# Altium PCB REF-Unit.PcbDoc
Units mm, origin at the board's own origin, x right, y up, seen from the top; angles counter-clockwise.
Board outline 28.96 x 18.29 mm, 4 copper layers (Top1, Signal2, Gnd3, Bottom4), stack 1.043 mm thick; 43 components, 73 nets, 248 pads, 219 vias.
Unrouted connection lines stored in the file: 57.
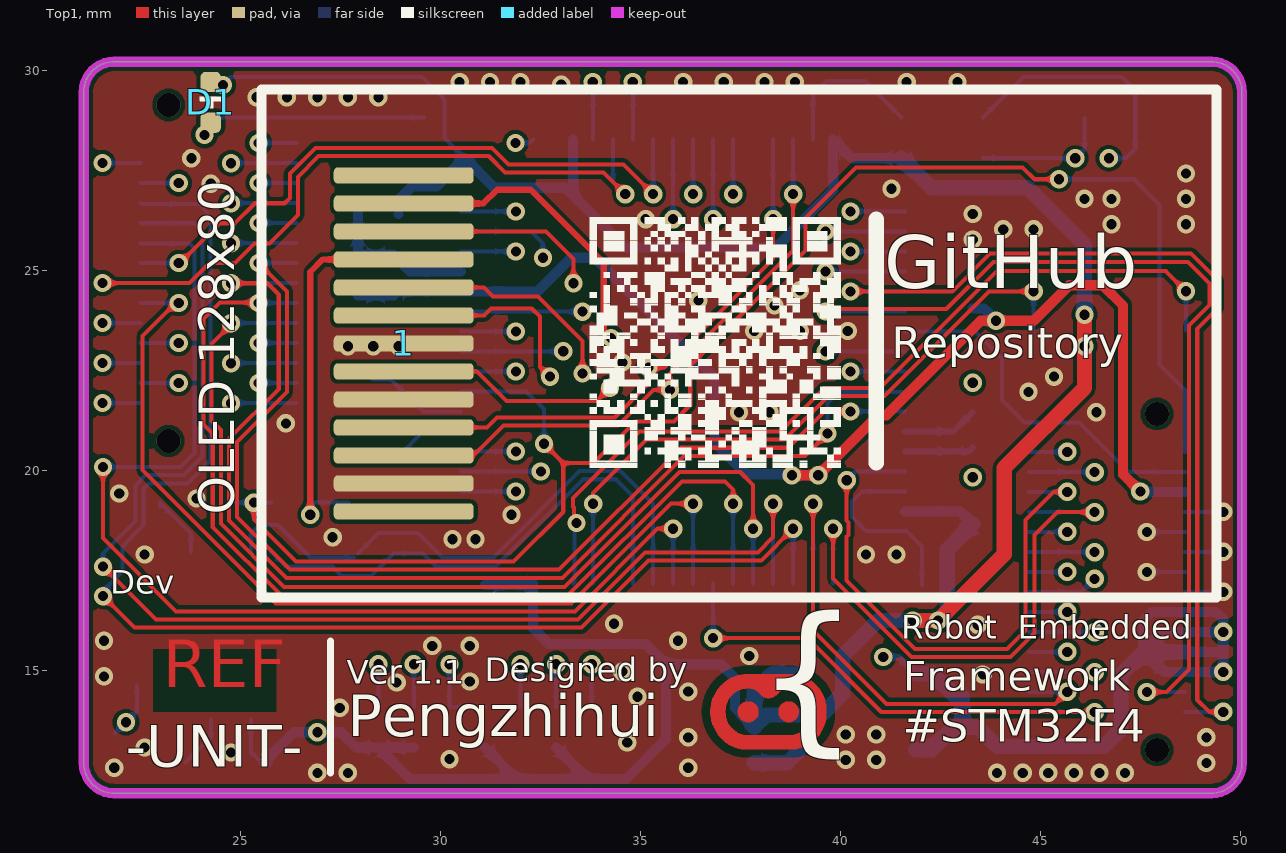
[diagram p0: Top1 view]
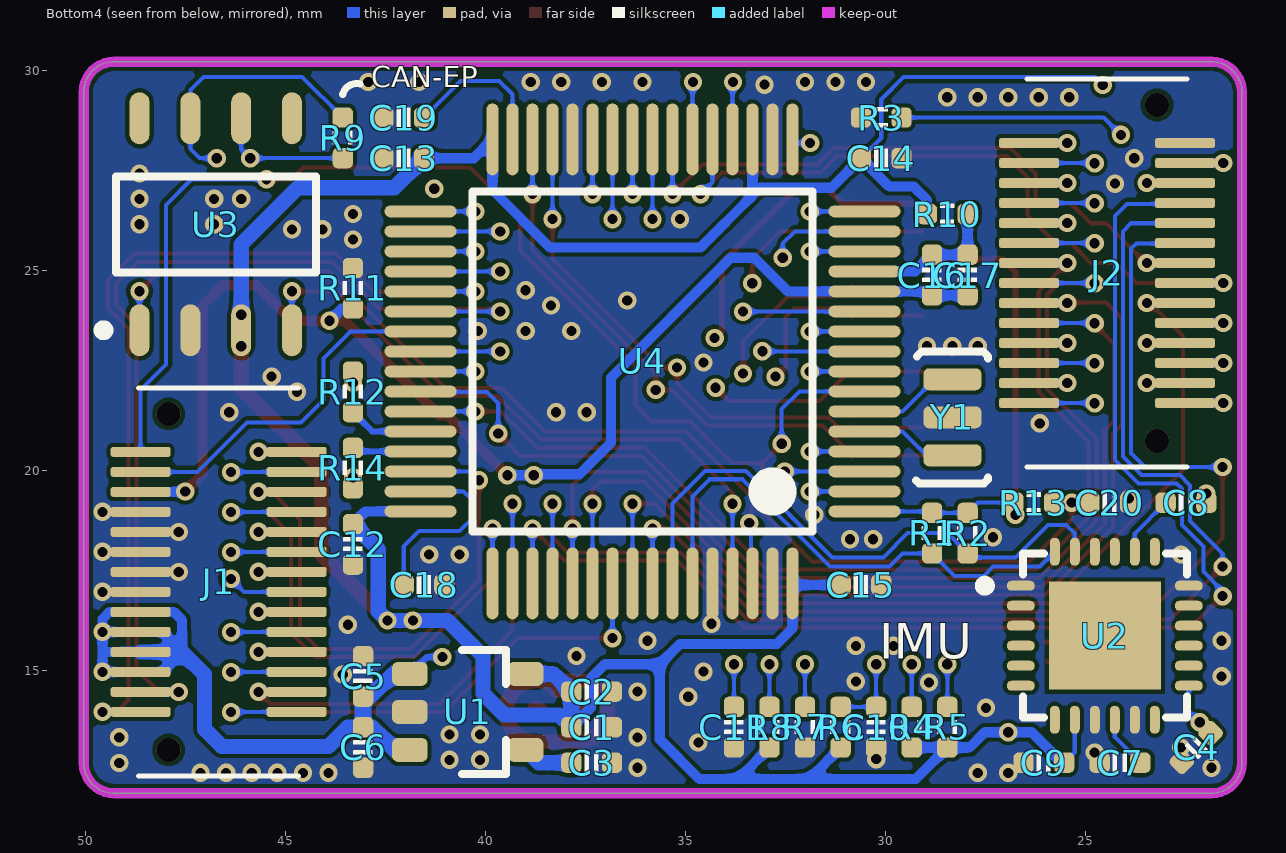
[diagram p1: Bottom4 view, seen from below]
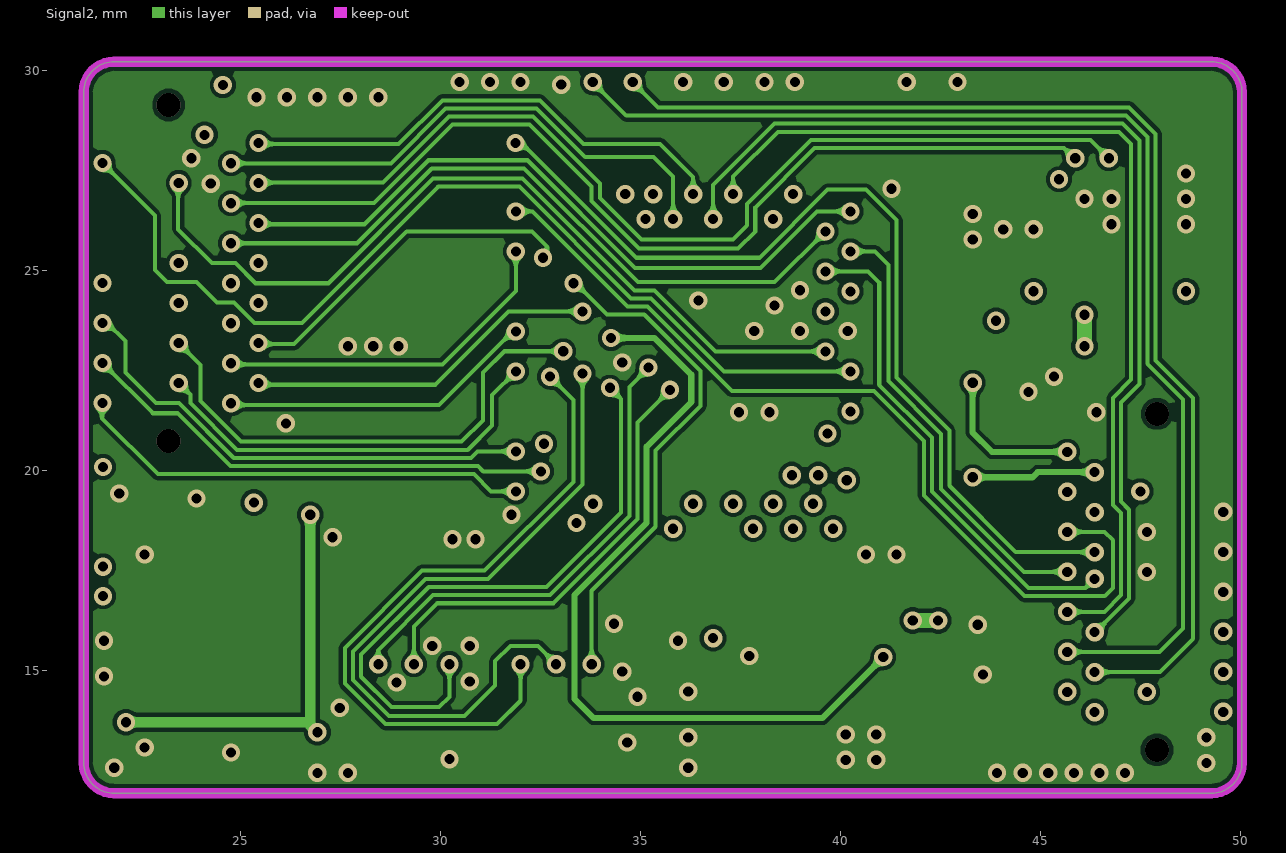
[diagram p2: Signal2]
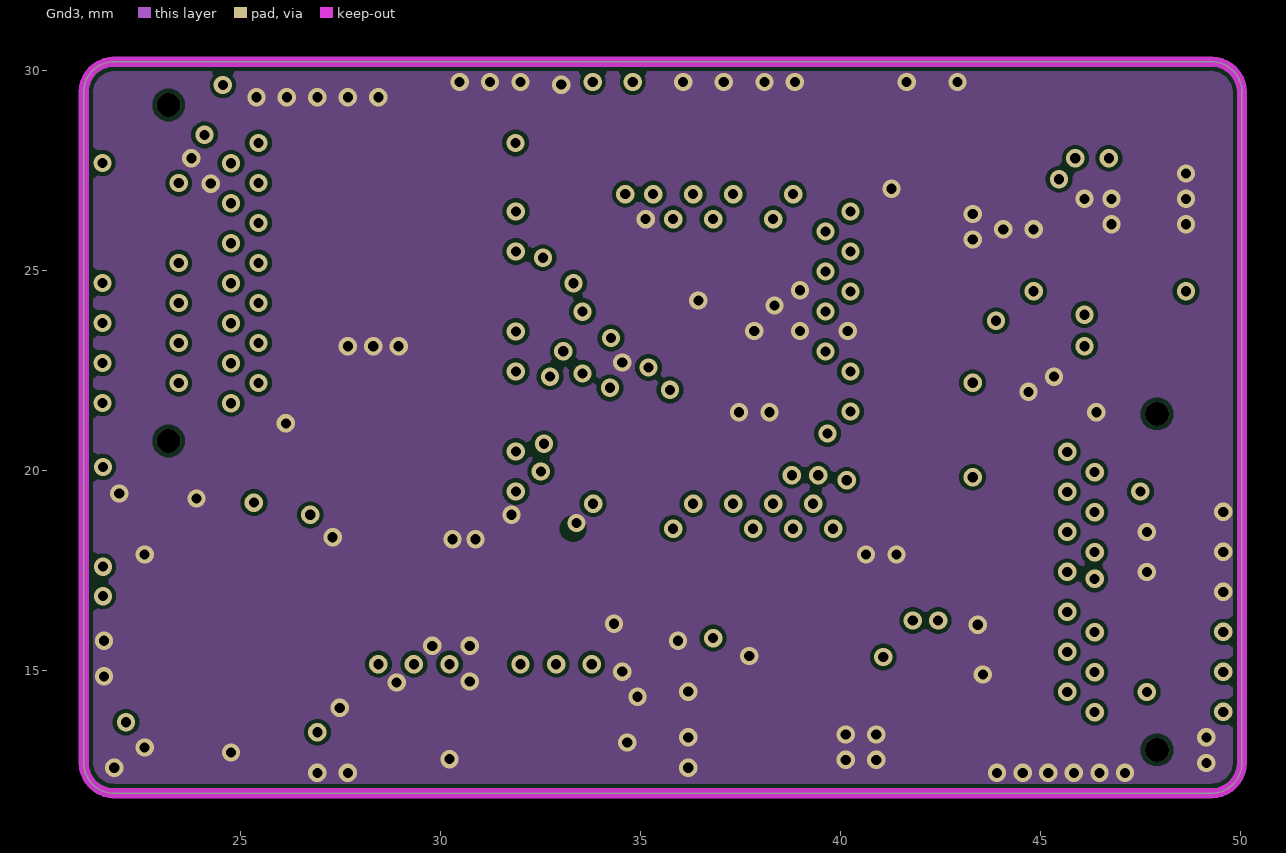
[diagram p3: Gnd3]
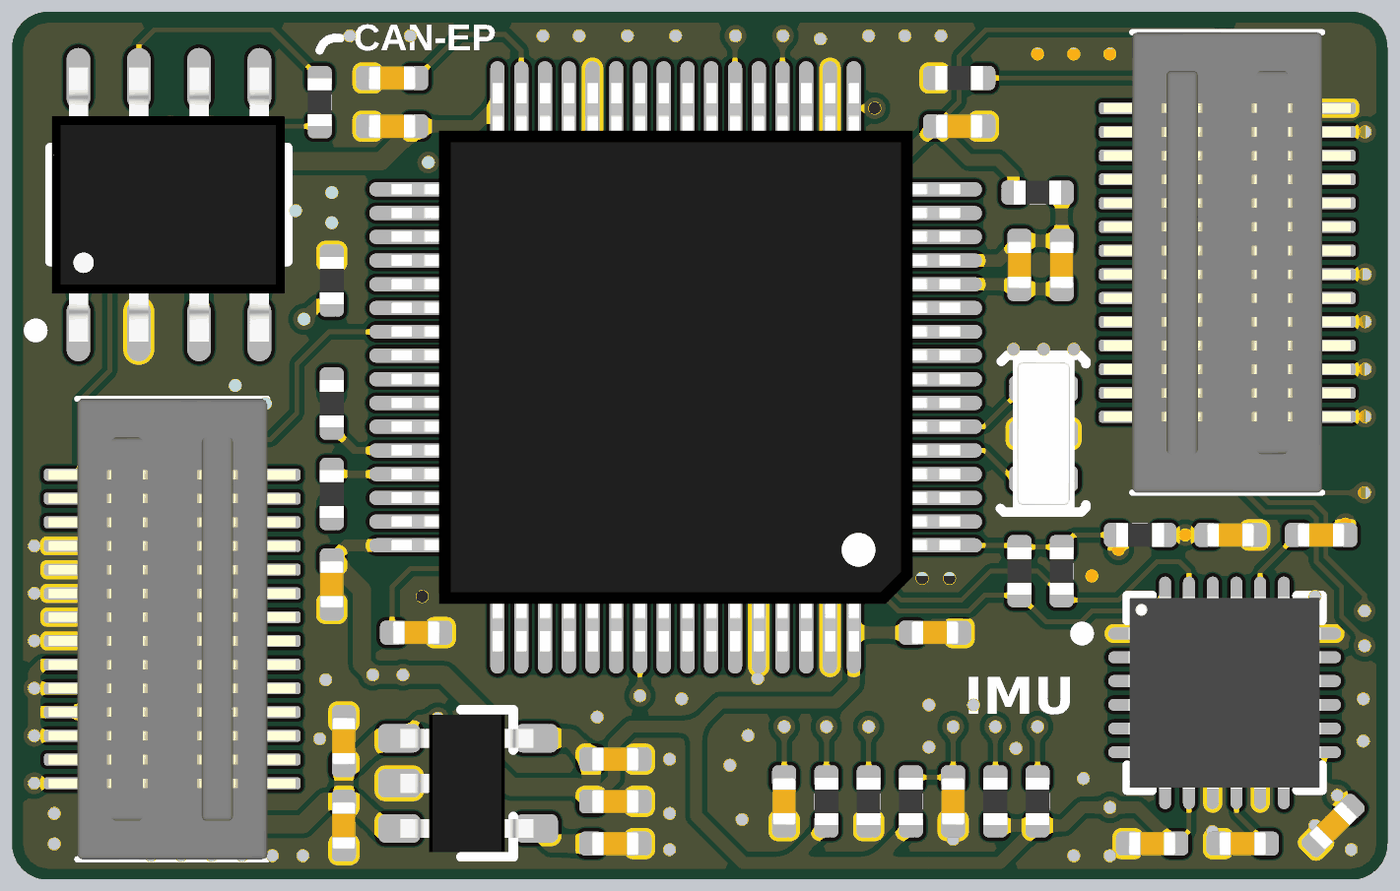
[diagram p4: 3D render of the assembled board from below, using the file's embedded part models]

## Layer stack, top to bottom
Top Solder: solder mask 0.0102, Solder Resist, Dk 3.5
Top1: signal copper 0.0356
Dielectric1: core 0.3, FR-4, Dk 4.2
Signal2: signal copper 0.036
Dielectric 4: prepreg 0.3, Dk 4.2
Gnd3: signal copper 0.036
Dielectric 3: core 0.3, Dk 4.2
Bottom4: signal copper 0.0356
Bottom Solder: solder mask 0.0102, Solder Resist, Dk 3.5

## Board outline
21.082,12.7 ccw(c21.844,12.7) 21.844,11.938 49.276,11.938 ccw(c49.276,12.7) 50.038,12.7 50.038,29.464 ccw(c49.276,29.464) 49.276,30.226 21.844,30.226 ccw(c21.844,29.464) 21.082,29.464

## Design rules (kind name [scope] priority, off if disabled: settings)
Clearance Clearance_Logo [InNetClass('Logo')] p1: gap=0.203 ignorepadtopadclearanceinfootprint=FALSE
Clearance [All] p2: gap=0.102 ignorepadtopadclearanceinfootprint=FALSE except(0: Arc-Hole Track-Hole SMDPad-Hole THPad-Hole Via-Hole Fill-Hole Poly-Hole Region-Hole Text-Hole)
ComponentClearance [All] p1: gap=0 collisioncheckmode=3 verticalgap=0 showdistances=FALSE
DiffPairsRouting [All] p1: maxlimit=0.229 minlimit=0.229 mostfreqgap=0.229 toplayer_minwidth=0.381 toplayer_maxwidth=0.381 toplayer_prefwidth=0.381 midlayer1_minwidth=0.381 midlayer1_maxwidth=0.381 midlayer1_prefwidth=0.381 midlayer2_minwidth=0.381 midlayer2_maxwidth=0.381 midlayer2_prefwidth=0.381 bottomlayer_minwidth=0.381 bottomlayer_maxwidth=0.381 bottomlayer_prefwidth=0.381 maxuncoupledlength=12.7
FanoutControl Fanout_BGA [All] p1: bgadir=Out bgaviamode=Centered fanoutstyle=Auto fanoutdirection=Alternating viagrid=0.025 // Fanout_BGA (Default Rule)
HoleSize [All] p1: absolutevalues=TRUE maxlimit=254 minlimit=0.203 maxpercent=80.000 minpercent=20.000
MinimumSolderMaskSliver [All] p1 off: minsoldermaskwidth=0.051
PlaneClearance [All] p1: clearance=0.203
PlaneConnect [All] p1: planeconnectstyle=Direct reliefexpansion=0.508 reliefentries=4 reliefconductorwidth=0.254 reliefairgap=0.254
PolygonConnect [All] p1: connectstyle=Direct reliefconductorwidth=0.254 reliefentries=4 polygonreliefangle="90 Angle" airgapwidth=0.254
RoutingVias [All] p1: holewidth=0.203 width=0.406 viastyle="Through Hole" minholewidth=0.152 minwidth=0.305 maxholewidth=0.711 maxwidth=1.27
SilkToSilkClearance [All] p1: silktosilkclearance=0
SilkToSolderMaskClearance [IsPad] p1: minsilkscreentomaskgap=0 clearancetoexposedcopper=TRUE
SolderMaskExpansion [All] p1: expansion=0.076 istentingtop=FALSE
Width Logo [InNetClass('Logo')] p1: maxlimit=2.54 minlimit=0.003 preferedwidth=0.254
Width GND [(InNet('AGND') OR InNet('GND'))] p2: maxlimit=1.27 minlimit=0.102 preferedwidth=0.254
Width VCC [(InNet('VDD_SYS_3.3V') OR InNet('VDD_AV_3.3V') OR InNet('VDD_5V') OR InNet('VDD1V2-SYS') OR InNet('VDD1V1-EPHY') OR InNet('VDD-CPUX') OR InNet('VDD-CPUS') OR InNet('VDD-CPUFB') OR InNet('VCC-DRAM'))] p3: maxlimit=1.27 minlimit=0.102 preferedwidth=0.254
Width [All] p4: maxlimit=254 minlimit=0.102 preferedwidth=0.102
21 further rules are at their usual default settings.

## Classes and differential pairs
net class Logo: LOGO1 LOGO2 LOGO3
net class Encoder: ENCODER1_A_1 ENCODER1_B_1 ENCODER2_A_1 ENCODER2_B_1
net class CAN: CAN1_H_1 CAN1_L_1 CAN2_D_1 CAN2_R_1
net class GPIO: PA4_1 PA6_1 PB0_1 PB1_1 PC0_1 PC1_1 PC8_1 PC13_1 PC14_1 PC15_1
net class ADC: ADC1_1 ADC2_1 ADC3_1 ADC4_1
net class PWM: PWM_A1_1 PWM_A2_1 PWM_B1_1 PWM_B2_1
net class I2C: I2C_SCL_1 I2C_SDA_1
net class SPI: SPI1_MISO_1 SPI1_MOSI_1 SPI1_SCK_1 SPI3_MISO_1 SPI3_MOSI_1 SPI3_SCK_1
net class UART: UART1_Rx_1 UART1_Tx_1 UART4_Rx_1 UART4_Tx_1 UART5_Rx_1 UART5_Tx_1
net class USB: USB_DM_1 USB_DP_1

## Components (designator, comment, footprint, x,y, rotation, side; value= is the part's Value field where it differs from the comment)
1 "OLED-12880" OLED-12880 29.083,23.182 r180 top locked
C1 "0.1uF" CAP_0402 37.338,13.589 r0 bottom value=0.1u
C2 "10uF" CAP_0402 37.338,14.478 r0 bottom value=0.1u
C3 "10nF" CAP_0402 37.338,12.7 r0 bottom value=0.1u
C4 "10nF" CAP_0402 22.225,13.081 r315 bottom value=0.1u
C5 "10uF" CAP_0402 43.053,14.859 r270 bottom value=0.1u
C6 "0.1uF" CAP_0402 43.053,13.081 r90 bottom value=0.1u
C7 "0.1uF" CAP_0402 24.13,12.7 r0 bottom value=0.1u
C8 "2.2nF" CAP_0402 22.479,19.202 r0 bottom value=0.1u
C9 "0.1uF" CAP_0402 26.035,12.7 r180 bottom value=0.1u
C10 "10uF" CAP_0402 30.226,13.589 r90 bottom value=0.1u
C11 "10uF" CAP_0402 33.782,13.589 r90 bottom value=0.1u
C12 "0.1uF" CAP_0402 43.307,18.161 r90 bottom value=0.1u
C13 "0.1uF" CAP_0402 42.037,27.813 r180 bottom value=0.1u
C14 "0.1uF" CAP_0402 30.099,27.813 r0 bottom value=0.1u
C15 "0.1uF" CAP_0402 30.607,17.145 r0 bottom value=0.1u
C16 "0.1uF" CAP_0402 28.829,24.892 r90 bottom value=0.1u
C17 "10uF" CAP_0402 27.94,24.892 r90 bottom value=0.1u
C18 "10uF" CAP_0402 41.529,17.145 r0 bottom value=0.1u
C19 "10uF" CAP_0402 42.037,28.829 r180 bottom value=0.1u
C20 "0.1uF" CAP_0402 24.384,19.202 r0 bottom value=0.1u
D1 "color?" LED_0402_RED 24.257,29.21 r270 top
J1 "B2B-Connector-28P-0.5mm" B2B-0.5mm-28P-M 46.666,17.22 r270 bottom locked
J2 "B2B-Connector-28P-0.5mm" B2B-0.5mm-28P-M 24.454,24.944 r90 bottom
R1 "2K" RES_0402 28.829,18.44 r90 bottom value=22R
R2 "2K" RES_0402 27.94,18.44 r90 bottom value=22R
R3 "2K" RES_0402 30.099,28.829 r180 bottom value=22R
R4 "4.7K" RES_0402 29.337,13.589 r270 bottom value=22R
R5 "4.7K" RES_0402 28.448,13.589 r270 bottom value=22R
R6 "10K" RES_0402 31.115,13.589 r270 bottom value=22R
R7 "560K" RES_0402 32.004,13.589 r270 bottom value=22R
R8 "4.7K" RES_0402 32.893,13.589 r270 bottom value=22R
R9 "120R/NC" RES_0402 43.561,28.321 r270 bottom value=22R
R10 "0R" RES_0402 28.448,26.416 r0 bottom value=22R
R11 "0R" RES_0402 43.307,24.562 r90 bottom value=22R
R12 "22R" RES_0402 43.307,21.971 r270 bottom
R13 "10K" RES_0402 26.289,19.202 r0 bottom value=22R
R14 "22R" RES_0402 43.307,20.066 r90 bottom
U1 "LP2992 3V3" SOT23-5 40.386,13.97 r180 bottom
U2 "MPU6050" QFN-24 24.511,15.875 r180 bottom
U3 "SN65HVD232D" SO-8 46.736,26.162 r90 bottom
U4 "STM32F405RGT6" LQFP-64_N 36.068,22.733 r0 bottom locked
Y1 "8MHz" 晶振-3P 28.321,21.336 r90 bottom

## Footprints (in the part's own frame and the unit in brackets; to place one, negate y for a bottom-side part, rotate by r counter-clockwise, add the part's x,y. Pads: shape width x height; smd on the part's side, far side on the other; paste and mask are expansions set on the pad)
B2B-0.5mm-28P-M [mm]
  rrect50% 0.25x1.5 smd: 1(-3.251,1.95) 2(-3.251,-1.95) 3(-2.751,1.95) 4(-2.751,-1.95) 5(-2.251,1.95) 6(-2.251,-1.95) 7(-1.751,1.95) 8(-1.751,-1.95) 9(-1.251,1.95) 10(-1.251,-1.95) 11(-0.751,1.95) 12(-0.751,-1.95) 13(-0.251,1.95) 14(-0.251,-1.95) 15(0.249,1.95) 16(0.249,-1.95) 17(0.749,1.95) 18(0.749,-1.95) 19(1.249,1.95) 20(1.249,-1.95) 21(1.749,1.95) 22(1.749,-1.95) 23(2.249,1.95) 24(2.249,-1.95) 25(2.749,1.95) 26(2.749,-1.95) 27(3.249,1.95) 28(3.249,-1.95)
  round 0.6 hole 0.6 unplated: ""(-4.2,-1.25) ""(4.2,-1.25)
  silkscreen extent -4.85,-2 4.85,2, body extent -4.85,-2.6 4.85,2.6, height 2.7
CAP_0402 [mil]
  rrect50% 20x20 smd: 1(-20,0) 2(20,0)
  silkscreen extent -6,-9 6,9, body extent -20,-10 20,10, height 20
LED_0402_RED [mil]
  rrect50% 20x20 smd: 1(-20,0) 2(20,0)
  silkscreen extent -6,-11 6,10, body extent -20,-10 20,10, height 18
LQFP-64_N [mm] "Thin QFP, 64-Leads, Body 10x10mm, Pitch 0.5mm, IPC Medium Density"
  oval 1.8x0.3 smd: 1(-5.55,3.75) 2(-5.55,3.25) 3(-5.55,2.75) 4(-5.55,2.25) 5(-5.55,1.75) 6(-5.55,1.25) 7(-5.55,0.75) 8(-5.55,0.25) 9(-5.55,-0.25) 10(-5.55,-0.75) 11(-5.55,-1.25) 12(-5.55,-1.75) 13(-5.55,-2.25) 14(-5.55,-2.75) 15(-5.55,-3.25) 16(-5.55,-3.75) 33(5.55,-3.75) 34(5.55,-3.25) 35(5.55,-2.75) 36(5.55,-2.25) 37(5.55,-1.75) 38(5.55,-1.25) 39(5.55,-0.75) 40(5.55,-0.25) 41(5.55,0.25) 42(5.55,0.75) 43(5.55,1.25) 44(5.55,1.75) 45(5.55,2.25) 46(5.55,2.75) 47(5.55,3.25) 48(5.55,3.75)
  oval 0.3x1.8 smd: 17(-3.75,-5.55) 18(-3.25,-5.55) 19(-2.75,-5.55) 20(-2.25,-5.55) 21(-1.75,-5.55) 22(-1.25,-5.55) 23(-0.75,-5.55) 24(-0.25,-5.55) 25(0.25,-5.55) 26(0.75,-5.55) 27(1.25,-5.55) 28(1.75,-5.55) 29(2.25,-5.55) 30(2.75,-5.55) 31(3.25,-5.55) 32(3.75,-5.55) 49(3.75,5.55) 50(3.25,5.55) 51(2.75,5.55) 52(2.25,5.55) 53(1.75,5.55) 54(1.25,5.55) 55(0.75,5.55) 56(0.25,5.55) 57(-0.25,5.55) 58(-0.75,5.55) 59(-1.25,5.55) 60(-1.75,5.55) 61(-2.25,5.55) 62(-2.75,5.55) 63(-3.25,5.55) 64(-3.75,5.55)
  silkscreen extent -4.25,-4.25 4.25,4.25, body extent -5.99,-5.99 5.98,5.98, height 1.6
OLED-12880 [mm]
  rrect50% 3.5x0.4 smd: 1(0,-4.2) 2(0,-3.5) 3(0,-2.8) 4(0,-2.1) 5(0,-1.4) 6(0,-0.7) 7(0,0) 8(0,0.7) 9(0,1.4) 10(0,2.1) 11(0,2.8) 12(0,3.5) 13(0,4.2)
  silkscreen extent -20.32,-6.35 3.56,6.35, body extent -20.18,-6.25 7.54,6.25, height 1.55
QFN-24 [mm] "QFN, 24-Leads, Body 4.1x4.1mm (max), Pitch 0.50mm, IPC Low Density"
  oval 0.7x0.25 smd: 1(-2.1,1.25) 2(-2.1,0.75) 3(-2.1,0.25) 4(-2.1,-0.25) 5(-2.1,-0.75) 6(-2.1,-1.25) 13(2.1,-1.25) 14(2.1,-0.75) 15(2.1,-0.25) 16(2.1,0.25) 17(2.1,0.75) 18(2.1,1.25)
  oval 0.25x0.7 smd: 7(-1.25,-2.1) 8(-0.75,-2.1) 9(-0.25,-2.1) 10(0.25,-2.1) 11(0.75,-2.1) 12(1.25,-2.1) 19(1.25,2.1) 20(0.75,2.1) 21(0.25,2.1) 22(-0.25,2.1) 23(-0.75,2.1) 24(-1.25,2.1)
  rect 2.8x2.7 smd: ""(0,0)
  silkscreen extent -3.13,-2.05 2.05,2.05, body extent -2.02,-2.02 2.02,2.02, height 0.95
RES_0402 [mil]
  rrect50% 20x20 smd: 1(-20,0) 2(20,0)
  silkscreen extent -7,-10 7,10, body extent -20,-10 20,10, height 14
SO-8 [mm]
  oval 1.3x0.5 smd: 1(-2.65,1.905) 2(-2.65,0.635) 3(-2.65,-0.635) 4(-2.65,-1.905) 5(2.65,-1.905) 6(2.65,-0.635) 7(2.65,0.635) 8(2.65,1.905)
  silkscreen extent -2.77,-2.5 1.2,2.93, body extent -2.89,-2.44 2.89,2.46, height 1.45
SOT23-5 [mm] "SOT23, 3-Leads, Body 3.1x3.0mm (max), Pitch 0.95mm, IPC Medium Density"
  rrect50% 0.889x0.6 smd: 1(-1.5,0.95) 2(-1.5,0) 3(-1.5,-0.95) 4(1.396,-0.95) 5(1.396,0.95)
  silkscreen extent -0.2,-1.55 0.9,1.55, body extent -1.48,-1.45 1.32,1.45, height 1.2
晶振-3P [mm] "贴片晶振"
  rrect50% 0.55x1.45 smd: 1(-0.95,0) 2(0,0) 3(0.95,0)
  silkscreen extent -1.65,-0.89 1.65,0.91, body extent -1.6,-0.89 1.65,0.89, height 0.7

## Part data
C1 C2 C3 C4 C5 C6 C7 C8 C9 C10 C11 C12 C13 C14 C15 C16 C17 C18 C19 C20: library part 电容-0402, "Capacitor"
D1: library part LED_0402, "LED"
R1 R2 R3 R4 R5 R6 R7 R8 R9 R10 R11 R12 R13 R14: library part 电阻-0402, "Resistor"
U1: library part LP2992, "LDO"
U2: "六轴传感器"
U3: Manufacturer="Texas Instruments", Manufacturer Part Number=SN65HVD232DR, Operating Temperature="-40°C ~ 85°C", Package / Case="8-SOIC (0.154\", 3.90mm Width)", Supplier Device Package=8-SOIC, Supplier Part Number 1=296-26344-2-ND, Voltage - Supply="3 V ~ 3.6 V"
U4: "ARM Cortex-M4 32-bit MCU+FPU, 210 DMIPS, 1024 kB Flash, 192 kB Internal RAM, 51 I/Os, 64-pin LQFP, -40 to 85 degC, Tray", I/Os (High Current)=51, Manufacturer=STMicroelectronics, Operating Frequency(F) (Processor speed) (MHz)=168, Supplier Part Number 1=497-11767-ND, Supply Voltage(Vcc) max (V)=3.6, Supply Voltage(Vcc) min (V)=1.8
Y1: library part 晶振-3Pin, "村田贴片"

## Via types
v1: diameter 0.457, hole 0.254, Top1 to Bottom4, tented both sides, 219 vias

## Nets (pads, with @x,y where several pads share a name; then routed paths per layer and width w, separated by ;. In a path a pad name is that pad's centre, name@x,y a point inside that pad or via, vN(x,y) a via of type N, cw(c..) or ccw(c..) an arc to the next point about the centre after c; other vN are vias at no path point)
3V3: 1.4 C1.2 C2.2 C4.1 C9.2 C12.2 C13.2 C14.2 C15.2 D1.1 R1.2 R2.2 R4.2 R5.2 R6.2 R8.2 R10.2 R13.2 U1.5 U2.8 U2.13 U3.3 U4.1 U4.19 U4.32 U4.48 U4.64 | length 107.9
  Top1 w0.152: v1(26.746,18.898) 26.746,24.968 27.06,25.282 1.4
  Top1 w0.381: v1(41.808,16.256) v1(42.443,16.256) 44.094,17.907 44.094,20.066 46.101,22.073 v1(46.101,23.114) v1(46.101,23.901)
  Signal2 w0.254: v1(22.138,13.713) 26.673,13.713 v1(26.924,13.462) 26.746,13.64 v1(26.746,18.898)
  Signal2 w0.381: v1(41.808,16.256) v1(42.443,16.256) ; v1(46.101,23.114) v1(46.101,23.901)
  Bottom4 w0.102: C4.1 v1(22.138,13.713) 22.411,13.985 U2.13 ; v1(24.562,29.642) 24.765,29.845 29.54,29.845 30.099,29.286 30.099,28.321 C14.2 ; U2.8 25.261,12.966 C9.2 ; v1(26.746,18.898) 26.797,18.948 R13.2 27.686,19.202 R2.2 R1.2 ; R1.2@28.947,18.983 U4.1
  Bottom4 w0.254: C9.2@25.578,12.7 26.34,13.462 v1(26.924,13.462) 27.508,13.462 27.889,13.081 R5.2 ; R10.2 28.956,26.772 29.286,27.102 29.896,27.102 C14.2 31.344,27.076 33.122,27.076 33.318,26.88 ; R4.2 R5.2 ; R6.2 31.902,12.294 ; C15.2 U4.64@32.28,17.145 ; U4.64 32.318,16.059 32.705,15.672 35.128,15.672 35.636,15.164 ; R8.2 33.68,12.294 ; U4.19 33.318,26.88 ; C1.2 37.363,14.072 37.363,14.808 37.008,15.164 35.636,15.164 ; C13.2 40.288,27.813 U4.32 39.818,27.016 38.379,25.578 34.62,25.578 33.318,26.88 ; U4.48 42.993,18.983 C12.2 ; R5.2 29.235,12.294 31.902,12.294 ; 31.902,12.294 33.68,12.294 ; 33.68,12.294 34.646,12.294 35.636,13.284 35.636,15.164
  Bottom4 w0.381: U1.5 38.288,14.92 C2.2 C1.2 38.151,13.894 39.522,13.894 40.056,14.427 40.056,15.367 40.945,16.256 v1(41.808,16.256) v1(42.443,16.256) 42.672,16.485 42.672,18.034 C12.2 ; C13.2 42.266,27.076 44.679,27.076 46.101,25.654 v1(46.101,23.901)
ADC1_1: J2.1 U4.10 | length 10.9
  Signal2 w0.102: v1(24.765,21.687) 24.811,21.641 29.964,21.641 31.806,23.483 v1(31.886,23.483)
  Bottom4 w0.102: v1@24.771,21.693 J2.1 ; U4.10 v1(31.886,23.483)
ADC2_1: J2.3 U4.11 | length 12.9
  Signal2 w0.102: v1(25.451,22.195) 25.497,22.149 29.87,22.149 31.705,23.983 33.548,23.983 v1(33.553,23.978)
  Bottom4 w0.102: v1(25.451,22.195) 25.453,22.193 J2.3 ; U4.11 30.523,23.978 v1(33.553,23.978)
ADC3_1: J2.25 U4.24 | length 17
  Signal2 w0.102: v1(24.765,27.687) v1(24.765,27.687) 28.761,27.686 30.132,29.058 32.401,29.058 33.62,27.838 35.331,27.838 35.818,27.352 v1(35.818,26.29)
  Bottom4 w0.102: v1(24.765,27.687) 24.771,27.693 J2.25 ; v1(35.818,26.29) U4.24
ADC4_1: J2.27 U4.25 | length 14.9
  Signal2 w0.102: v1(25.451,28.195) 25.477,28.169 28.956,28.169 30.048,29.261 32.485,29.261 33.577,28.169 35.488,28.169 36.318,27.338 v1(36.318,26.915)
  Bottom4 w0.102: v1(25.451,28.195) v1(25.451,28.195) J2.27 ; v1(36.318,26.915) U4.25
AGND: C16.1 C17.1 J1.6 R11.1 U4.12 | length 32.2
  Top1 w0.254: v1(38.786,19.888) v1(39.446,19.888) 40.945,21.387 41.148,21.387 43.51,23.749 v1(43.891,23.749) 44.831,23.749 45.72,24.638 46.558,24.638 47.066,24.13 47.066,19.914 v1(47.498,19.482)
  Bottom4 w0.254: C17.1 C16.1 28.928,24.483 U4.12 32.433,24.483 33.274,25.324 33.858,25.324 36.855,22.327 36.855,20.701 37.643,19.914 38.786,19.914 38.811,19.888 v1(39.446,19.888) ; R11.1 43.586,24.054 v1(43.891,23.749) ; v1(47.498,19.482) 47.509,19.471 J1.6
AVCC: C16.2 C17.2 R10.1 U4.13 | length 3.8
  Bottom4 w0.254: R10.1 C17.2 C16.2 29.246,24.983 U4.13
CAN1_D_1: U3.1 U4.62 | length 21.1
  Top1 w0.102: v1(33.401,18.694) 33.341,18.755 33.341,19.075 33.318,19.098 33.318,19.323 34.976,20.98 38.506,20.98 39.599,22.073 40.996,22.073 43.917,24.994 48.133,24.994 v1(48.641,24.486)
  Bottom4 w0.102: U4.62 33.356,17.221 33.356,18.649 v1(33.401,18.694) ; U3.1 v1(48.641,24.486)
CAN1_H_1: J2.23 R9.1 U3.7 | length 32.5
  Signal2 w0.102: v1(25.451,27.195) 25.459,27.203 28.566,27.203 30.217,28.854 32.317,28.854 33.985,27.186 33.985,26.822 35.027,25.781 37.313,25.781 37.668,26.137 37.668,26.67 39.268,28.27 46.253,28.27 v1(46.711,27.813)
  Bottom4 w0.102: v1(25.451,27.195) 25.453,27.193 J2.23 ; R9.1 44.577,29.845 47.041,29.845 47.371,29.515 U3.7 47.371,28.042 47.142,27.813 v1(46.711,27.813)
CAN1_L_1: J2.21 R9.2 U3.6 | length 30
  Signal2 w0.102: v1(24.765,26.687) 24.773,26.695 28.345,26.695 30.301,28.651 32.233,28.651 33.782,27.102 33.782,26.738 34.968,25.552 37.44,25.552 37.871,25.984 37.871,26.586 39.353,28.067 45.588,28.067 45.842,27.813 v1(45.872,27.813)
  Bottom4 w0.102: v1@24.771,26.693 J2.21 ; R9.2 v1(45.872,27.813) 46.101,28.042 U3.6
CAN1_R_1: U3.4 U4.61 | length 16.3
  Top1 w0.102: v1(33.818,19.176) 33.818,19.442 35.154,20.777 38.608,20.777 39.7,21.869 41.097,21.869 43.713,24.486 v1(44.831,24.486)
  Bottom4 w0.102: U4.61 v1(33.818,19.176) ; U3.4 v1(44.831,24.486)
CAN2_D_1: J2.17 U4.34 | length 21
  Signal2 w0.102: v1(24.765,25.687) 27.911,25.687 29.783,27.559 32.09,27.559 34.934,24.714 38.356,24.714 v1(39.625,25.983)
  Bottom4 w0.102: v1@24.771,25.693 J2.17 ; v1(39.625,25.983) U4.34
CAN2_R_1: J2.19 U4.33 | length 19.5
  Signal2 w0.102: v1(25.451,26.195) 25.484,26.162 28.099,26.162 29.699,27.762 32.174,27.762 34.866,25.07 38.006,25.07 39.42,26.483 v1(40.25,26.483)
  Bottom4 w0.102: v1(25.451,26.195) 25.453,26.193 J2.19 ; v1(40.25,26.483) U4.33
ENCODER1_A_1: J1.25 U4.50 | length 13.4
  Top1 w0.102: v1(39.318,19.176) 39.318,16.003 41.148,14.173 45.37,14.173 v1(45.669,14.472)
  Bottom4 w0.102: U4.50 v1(39.318,19.176) ; J1.25 45.667,14.471 v1(45.669,14.472)
ENCODER1_B_1: J1.27 U4.55 | length 13.3
  Top1 w0.102: v1(36.818,15.815) 39.176,15.815 41.021,13.97 46.349,13.97 v1(46.355,13.964)
  Bottom4 w0.102: v1(36.818,15.815) U4.55 ; J1.27 v1@46.349,13.971
ENCODER2_A_1: J1.28 U4.37 | length 23.6
  Top1 w0.102: v1(40.25,24.483) 42.796,24.483 43.739,25.425 48.768,25.425 49.428,24.765 49.428,24.054 48.92,23.546 48.92,14.275 49.223,13.972 v1(49.569,13.972)
  Bottom4 w0.102: v1(40.25,24.483) U4.37 ; J1.28 49.567,13.971 v1(49.569,13.972)
ENCODER2_B_1: J1.26 U4.38 | length 24.4
  Top1 w0.102: v1(39.625,23.983) 39.687,24.045 42.646,24.045 43.823,25.222 48.684,25.222 49.225,24.681 49.225,24.138 48.717,23.63 48.717,15.037 48.149,14.469 v1(47.662,14.469)
  Bottom4 w0.102: v1(39.625,23.983) U4.38 ; v1(47.662,14.469) 47.664,14.471 J1.26
GND: 1.7 1.9 1.12 C1.1 C2.1 C3.1 C4.2 C5.1 C6.1 C7.2 C8.1 C9.1 C10.1 C11.1 C12.1 C13.1 C14.1 C15.1 C18.1 C19.1 C20.1 J1.8 J1.10 J1.12 J1.14 J1.16 J2.28 R3.1 R7.2 R11.2 U1.2 U2.1 U2.9 U2.11 U2.18 U3.2 U4.18 U4.28 U4.60 U4.63 Y1.2 | length 4.8
  Bottom4 w0.102: v1(47.662,17.469) 47.664,17.471 J1.14 ; v1(47.662,18.469) 47.664,18.471 J1.10 ; J1.16 49.567,16.971 v1(49.569,16.972) ; J1.12 49.567,17.971 v1(49.569,17.972) ; J1.8 49.567,18.971 v1(49.569,18.972)
  other v1: 26.924,12.446 27.686,12.446 43.917,12.446 44.557,12.446 45.197,12.446 45.837,12.446 46.477,12.446 47.117,12.446 21.844,12.573 36.195,12.573 49.149,12.695 30.226,12.789 40.132,12.772 40.894,12.772 24.765,12.954 22.606,13.081 34.671,13.208 36.195,13.335 49.149,13.335 40.132,13.407 40.894,13.407 27.483,14.072 34.925,14.351 36.195,14.478 28.905,14.707 30.734,14.732 21.59,14.859 43.561,14.908 34.544,14.977 37.719,15.367 29.794,15.621 30.734,15.621 21.59,15.748 35.941,15.748 43.434,16.151 34.341,16.176 22.606,17.907 40.64,17.907 41.402,17.907 30.302,18.288 30.878,18.288 27.305,18.339 31.775,18.898 23.901,19.304 21.971,19.431 26.137,21.184 37.465,21.463 38.227,21.463 46.399,21.463 44.704,21.971 45.339,22.352 34.544,22.704 27.686,23.114 28.321,23.114 28.956,23.114 37.846,23.495 38.989,23.495 40.184,23.495 38.354,24.13 36.449,24.257 38.989,24.511 43.307,25.781 44.069,26.035 44.831,26.035 46.776,26.162 48.641,26.162 35.131,26.29 43.307,26.416 46.101,26.797 46.776,26.797 48.641,26.797 41.275,27.051 24.257,27.178 48.641,27.432 23.774,27.813 25.4,29.337 26.162,29.337 26.924,29.337 27.686,29.337 28.448,29.337 33.02,29.652 30.48,29.718 31.242,29.718 32.004,29.718 36.068,29.718 37.084,29.718 38.1,29.718 38.862,29.718 41.656,29.718 42.926,29.718
I2C_SCL_1: J2.26 U4.41 | length 26.8
  Signal2 w0.102: v1(21.551,27.695) 22.86,26.386 22.86,25.019 23.165,24.714 23.901,24.714 24.409,24.206 24.841,24.206 25.349,23.698 26.543,23.698 29.947,27.102 31.972,27.102 34.766,24.308 35.264,24.308 37.089,22.483 38.858,22.483 v1(40.25,22.483)
  Bottom4 w0.102: v1(21.551,27.695) 21.553,27.693 J2.26 ; v1(40.25,22.483) U4.41
I2C_SDA_1: J2.24 U4.40 | length 23.7
  Signal2 w0.102: v1(23.458,27.192) 23.444,27.178 23.444,26.035 24.288,25.192 24.872,25.192 25.376,24.687 27.199,24.687 29.817,27.305 32.056,27.305 34.85,24.511 35.348,24.511 36.876,22.983 v1(39.625,22.983)
  Bottom4 w0.102: J2.24 23.456,27.193 v1(23.458,27.192) ; v1(39.625,22.983) U4.40
IMU_SCL_1: R2.1 U2.23 U4.58 | length 14.5
  Bottom4 w0.102: U2.23 25.261,18.428 25.476,18.644 25.933,18.644 26.746,17.831 R2.1@27.838,17.831 ; R2.1 28.448,18.44 29.439,18.44 30.048,17.831 31.324,17.831 33.483,19.99 34.504,19.99 35.318,19.176 U4.58
IMU_SDA_1: R1.1 U2.24 U4.59 | length 12.9
  Bottom4 w0.102: U2.24 26.134,17.602 27.301,17.602 27.529,17.374 28.27,17.374 R1.1 29.566,17.932 29.896,17.602 31.383,17.602 33.567,19.787 34.392,19.787 34.818,19.36 U4.59
LOGO1:  | length 202.5
  Top1 w0.013: 36.751,13.913 37.132,13.913 ; 36.751,13.926 37.132,13.926 ; 36.751,13.938 37.12,13.938 ; 36.751,13.951 37.12,13.951 ; 36.751,13.964 37.12,13.964 ; 36.751,13.976 37.12,13.976 ; 36.751,13.989 37.12,13.989 ; 36.751,14.002 37.12,14.002 ; 36.751,14.014 37.12,14.014 ; 36.751,14.027 37.12,14.027 ; 36.751,14.04 37.132,14.04 ; 36.764,13.837 37.132,13.837 ; 36.764,13.849 37.132,13.849 ; 36.764,13.862 37.132,13.862 ; 36.764,13.875 37.132,13.875 ; 36.764,13.887 37.132,13.887 ; 36.764,13.9 37.132,13.9 ; 36.764,14.053 37.132,14.053 ; 36.764,14.065 37.132,14.065 ; 36.764,14.078 37.132,14.078 ; 36.764,14.091 37.132,14.091 ; 36.764,14.103 37.132,14.103 ; 36.764,14.116 37.132,14.116 ; 36.777,13.748 37.158,13.748 ; 36.777,13.76 37.158,13.76 ; 36.777,13.773 37.158,13.773 ; 36.777,13.786 37.158,13.786 ; 36.777,13.799 37.145,13.799 ; 36.777,13.811 37.145,13.811 ; 36.777,13.824 37.132,13.824 ; 36.777,14.129 37.132,14.129 ; 36.777,14.141 37.132,14.141 ; 36.777,14.154 37.145,14.154 ; 36.777,14.167 37.145,14.167 ; 36.777,14.18 37.158,14.18 ; 36.777,14.192 37.158,14.192 ; 36.777,14.205 37.158,14.205 ; 36.789,13.722 37.17,13.722 ; 36.789,13.735 37.17,13.735 ; 36.789,14.218 37.17,14.218 ; 36.789,14.23 37.17,14.23 ; 36.789,14.243 37.183,14.243 ; 36.789,14.256 37.183,14.256 ; 36.802,13.659 37.208,13.659 ; 36.802,13.672 37.196,13.672 ; 36.802,13.684 37.183,13.684 ; 36.802,13.697 37.183,13.697 ; 36.802,13.71 37.183,13.71 ; 36.802,14.268 37.183,14.268 ; 36.802,14.281 37.196,14.281 ; 36.802,14.294 37.208,14.294 ; 36.802,14.307 37.208,14.307 ; 36.815,13.633 37.234,13.633 ; 36.815,13.646 37.208,13.646 ; 36.815,14.319 37.221,14.319 ; 36.815,14.332 37.234,14.332 ; 36.827,13.595 37.259,13.595 ; 36.827,13.608 37.247,13.608 ; 36.827,13.621 37.234,13.621 ; 36.827,14.345 37.234,14.345 ; 36.827,14.357 37.247,14.357 ; 36.84,13.57 37.272,13.57 ; 36.84,13.583 37.272,13.583 ; 36.84,14.37 37.272,14.37 ; 36.84,14.383 37.272,14.383 ; 36.853,14.395 37.297,14.395 ; 36.866,13.519 37.335,13.519 ; 36.866,13.532 37.323,13.532 ; 36.866,13.545 37.31,13.545 ; 36.866,13.557 37.297,13.557 ; 36.866,14.408 37.297,14.408 ; 36.866,14.421 37.31,14.421 ; 36.866,14.434 37.323,14.434 ; 36.878,13.506 37.348,13.506 ; 36.878,14.446 37.348,14.446 ; 36.891,13.481 37.374,13.481 ; 36.891,13.494 37.374,13.494 ; 36.891,14.459 37.361,14.459 ; 36.891,14.472 37.374,14.472 ; 36.904,13.468 37.412,13.468 ; 36.904,14.484 37.399,14.484 ; 36.904,14.497 37.412,14.497 ; 36.916,13.443 37.462,13.443 ; 36.916,13.456 37.424,13.456 ; 36.916,14.51 37.45,14.51 ; 36.916,14.522 37.462,14.522 ; 36.929,13.43 37.488,13.43 ; 36.929,14.535 37.513,14.535 ; 36.942,13.405 37.577,13.405 ; 36.942,13.418 37.539,13.418 ; 36.942,14.548 37.539,14.548 ; 36.954,13.392 39.456,13.392 ; 36.954,14.561 37.628,14.561 ; 36.967,13.379 39.444,13.379 ; 36.967,14.573 39.456,14.573 ; 36.967,14.586 39.431,14.586 ; 36.98,13.367 39.431,13.367 ; 36.98,14.599 39.431,14.599 ; 36.993,13.354 39.431,13.354 ; 36.993,14.611 39.406,14.611 ; 37.005,13.341 39.406,13.341 ; 37.005,14.624 39.406,14.624 ; 37.018,13.316 39.38,13.316 ; 37.018,13.329 39.393,13.329 ; 37.018,14.637 39.393,14.637 ; 37.031,14.649 39.38,14.649 ; 37.043,13.303 39.367,13.303 ; 37.056,13.291 39.367,13.291 ; 37.056,14.662 39.367,14.662 ; 37.056,14.675 39.355,14.675 ; 37.069,13.278 39.342,13.278 ; 37.069,14.688 39.342,14.688 ; 37.081,13.265 39.342,13.265 ; 37.094,13.252 39.317,13.252 ; 37.094,14.7 39.329,14.7 ; 37.094,14.713 39.317,14.713 ; 37.107,13.24 39.304,13.24 ; 37.12,13.227 39.279,13.227 ; 37.12,14.726 39.291,14.726 ; 37.132,13.214 39.266,13.214 ; 37.132,14.738 39.291,14.738 ; 37.158,13.202 39.253,13.202 ; 37.158,14.751 39.266,14.751 ; 37.158,14.764 39.253,14.764 ; 37.183,13.189 39.24,13.189 ; 37.183,14.776 39.215,14.776 ; 37.196,13.176 39.215,13.176 ; 37.208,13.164 39.19,13.164 ; 37.208,14.789 39.215,14.789 ; 37.234,13.151 39.164,13.151 ; 37.234,14.802 39.177,14.802 ; 37.247,14.815 39.152,14.815 ; 37.259,13.138 39.152,13.138 ; 37.272,14.827 39.126,14.827 ; 37.297,13.125 39.113,13.125 ; 37.297,14.84 39.113,14.84 ; 37.323,13.113 39.101,13.113 ; 37.348,14.853 39.063,14.853 ; 37.361,13.1 39.05,13.1 ; 37.361,14.865 39.05,14.865 ; 37.374,13.087 39.037,13.087 ; 37.412,14.878 38.999,14.878 ; 37.424,13.075 38.974,13.075 ; 37.424,14.891 38.974,14.891 ; 37.462,13.062 38.936,13.062 ; 37.513,14.903 38.885,14.903 ; 37.526,13.049 38.898,13.049 ; 37.589,14.916 38.834,14.916 ; 37.755,14.561 38.656,14.561 ; 37.831,14.548 38.593,14.548 ; 37.856,14.535 38.567,14.535 ; 37.882,14.522 38.542,14.522 ; 37.894,14.51 38.517,14.51 ; 37.92,14.497 38.491,14.497 ; 37.932,14.484 38.478,14.484 ; 37.945,14.472 38.453,14.472 ; 37.97,14.446 38.453,14.446 ; 37.97,14.459 38.453,14.459 ; 37.983,14.434 38.428,14.434 ; 37.996,14.421 38.415,14.421 ; 38.009,14.408 38.402,14.408 ; 38.021,14.395 38.402,14.395 ; 38.034,14.383 38.377,14.383 ; 38.047,14.37 38.364,14.37 ; 38.072,14.345 38.326,14.345 ; 38.072,14.357 38.351,14.357 ; 38.123,14.332 38.288,14.332 ; 38.174,14.319 38.237,14.319 ; 38.783,14.561 39.456,14.561 ; 38.834,13.405 39.469,13.405 ; 38.872,13.418 39.482,13.418 ; 38.872,14.548 39.482,14.548 ; 38.885,14.535 39.482,14.535 ; 38.923,13.43 39.482,13.43 ; 38.936,13.443 39.482,13.443 ; 38.948,14.522 39.494,14.522 ; 38.974,14.51 39.494,14.51 ; 38.986,13.456 39.507,13.456 ; 38.999,13.468 39.507,13.468 ; 38.999,14.497 39.507,14.497 ; 39.012,14.484 39.507,14.484 ; 39.025,13.481 39.52,13.481 ; 39.037,13.494 39.52,13.494 ; 39.037,14.472 39.52,14.472 ; 39.05,14.459 39.533,14.459 ; 39.063,13.506 39.533,13.506 ; 39.063,14.446 39.533,14.446 ; 39.075,13.519 39.533,13.519 ; 39.088,13.532 39.545,13.532 ; 39.088,14.434 39.545,14.434 ; 39.101,13.545 39.558,13.545 ; 39.101,14.421 39.545,14.421 ; 39.113,13.557 39.558,13.557 ; 39.113,14.408 39.558,14.408 ; 39.126,13.57 39.558,13.57 ; 39.126,14.395 39.558,14.395 ; 39.139,13.583 39.571,13.583 ; 39.139,14.383 39.571,14.383 ; 39.152,13.595 39.571,13.595 ; 39.152,14.357 39.583,14.357 ; 39.152,14.37 39.571,14.37 ; 39.164,13.608 39.583,13.608 ; 39.177,13.621 39.596,13.621 ; 39.177,13.633 39.596,13.633 ; 39.177,14.345 39.583,14.345 ; 39.19,13.646 39.596,13.646 ; 39.19,14.319 39.596,14.319 ; 39.19,14.332 39.596,14.332 ; 39.202,13.659 39.596,13.659 ; 39.202,14.307 39.596,14.307 ; 39.215,13.672 39.609,13.672 ; 39.215,13.684 39.609,13.684 ; 39.215,14.268 39.621,14.268 ; 39.215,14.281 39.609,14.281 ; 39.215,14.294 39.609,14.294 ; 39.228,13.697 39.621,13.697 ; 39.228,13.71 39.621,13.71 ; 39.228,14.256 39.621,14.256 ; 39.24,13.722 39.621,13.722 ; 39.24,13.735 39.621,13.735 ; 39.24,14.205 39.621,14.205 ; 39.24,14.218 39.621,14.218 ; 39.24,14.23 39.621,14.23 ; 39.24,14.243 39.621,14.243 ; 39.253,13.748 39.634,13.748 ; 39.253,13.76 39.634,13.76 ; 39.253,13.773 39.634,13.773 ; 39.253,14.18 39.634,14.18 ; 39.253,14.192 39.634,14.192 ; 39.266,13.786 39.634,13.786 ; 39.266,13.799 39.634,13.799 ; 39.266,13.811 39.647,13.811 ; 39.266,13.824 39.647,13.824 ; 39.266,14.129 39.647,14.129 ; 39.266,14.141 39.647,14.141 ; 39.266,14.154 39.647,14.154 ; 39.266,14.167 39.647,14.167 ; 39.279,13.837 39.647,13.837 ; 39.279,13.849 39.647,13.849 ; 39.279,13.862 39.647,13.862 ; 39.279,13.875 39.647,13.875 ; 39.279,14.078 39.647,14.078 ; 39.279,14.091 39.647,14.091 ; 39.279,14.103 39.647,14.103 ; 39.279,14.116 39.647,14.116 ; 39.291,13.887 39.647,13.887 ; 39.291,13.9 39.647,13.9 ; 39.291,13.913 39.647,13.913 ; 39.291,13.926 39.647,13.926 ; 39.291,13.938 39.647,13.938 ; 39.291,13.951 39.647,13.951 ; 39.291,13.964 39.647,13.964 ; 39.291,13.976 39.647,13.976 ; 39.291,13.989 39.647,13.989 ; 39.291,14.002 39.647,14.002 ; 39.291,14.014 39.647,14.014 ; 39.291,14.027 39.647,14.027 ; 39.291,14.04 39.647,14.04 ; 39.291,14.053 39.647,14.053 ; 39.291,14.065 39.647,14.065
LOGO2:  | length 16.4
  Top1 w0.013: 37.437,13.951 37.945,13.951 ; 37.437,13.964 37.945,13.964 ; 37.437,13.976 37.945,13.976 ; 37.437,13.989 37.945,13.989 ; 37.437,14.002 37.945,14.002 ; 37.437,14.014 37.945,14.014 ; 37.45,13.887 37.945,13.887 ; 37.45,13.9 37.945,13.9 ; 37.45,13.913 37.945,13.913 ; 37.45,13.926 37.945,13.926 ; 37.45,13.938 37.945,13.938 ; 37.45,14.027 37.945,14.027 ; 37.45,14.04 37.945,14.04 ; 37.45,14.053 37.945,14.053 ; 37.45,14.065 37.945,14.065 ; 37.45,14.078 37.932,14.078 ; 37.462,13.862 37.932,13.862 ; 37.462,13.875 37.932,13.875 ; 37.462,14.091 37.932,14.091 ; 37.475,14.103 37.92,14.103 ; 37.475,14.116 37.92,14.116 ; 37.488,13.837 37.92,13.837 ; 37.488,13.849 37.92,13.849 ; 37.488,14.129 37.907,14.129 ; 37.488,14.141 37.894,14.141 ; 37.501,13.824 37.894,13.824 ; 37.513,13.799 37.869,13.799 ; 37.513,13.811 37.882,13.811 ; 37.513,14.154 37.882,14.154 ; 37.513,14.167 37.882,14.167 ; 37.526,13.786 37.856,13.786 ; 37.539,14.18 37.856,14.18 ; 37.551,13.773 37.831,13.773 ; 37.551,14.192 37.843,14.192 ; 37.564,13.76 37.831,13.76 ; 37.577,14.205 37.818,14.205 ; 37.589,13.748 37.805,13.748 ; 37.589,14.218 37.805,14.218 ; 37.615,13.735 37.767,13.735 ; 37.615,14.23 37.78,14.23 ; 37.64,13.722 37.742,13.722
LOGO3:  | length 16.5
  Top1 w0.013: 38.453,13.887 38.936,13.887 ; 38.453,13.9 38.948,13.9 ; 38.453,13.913 38.948,13.913 ; 38.453,13.926 38.961,13.926 ; 38.453,13.938 38.961,13.938 ; 38.453,13.951 38.961,13.951 ; 38.453,13.964 38.961,13.964 ; 38.453,13.976 38.961,13.976 ; 38.453,13.989 38.961,13.989 ; 38.453,14.002 38.961,14.002 ; 38.453,14.014 38.961,14.014 ; 38.453,14.027 38.961,14.027 ; 38.453,14.04 38.961,14.04 ; 38.453,14.053 38.948,14.053 ; 38.453,14.065 38.948,14.065 ; 38.466,14.078 38.936,14.078 ; 38.466,14.091 38.936,14.091 ; 38.478,13.849 38.923,13.849 ; 38.478,13.862 38.936,13.862 ; 38.478,13.875 38.936,13.875 ; 38.478,14.103 38.936,14.103 ; 38.478,14.116 38.923,14.116 ; 38.491,13.837 38.91,13.837 ; 38.491,14.129 38.91,14.129 ; 38.504,13.811 38.898,13.811 ; 38.504,13.824 38.91,13.824 ; 38.504,14.141 38.91,14.141 ; 38.504,14.154 38.885,14.154 ; 38.529,13.799 38.885,13.799 ; 38.529,14.167 38.885,14.167 ; 38.542,13.786 38.872,13.786 ; 38.542,14.18 38.859,14.18 ; 38.555,14.192 38.859,14.192 ; 38.567,13.76 38.834,13.76 ; 38.567,13.773 38.847,13.773 ; 38.58,14.205 38.821,14.205 ; 38.593,13.748 38.821,13.748 ; 38.605,14.218 38.809,14.218 ; 38.618,14.23 38.796,14.23 ; 38.631,13.735 38.783,13.735 ; 38.656,13.722 38.758,13.722
Net1_3: 1.3 C11.2 | length 18.7
  Top1 w0.102: 1.3 32.641,25.982 33.325,25.298 v1(33.325,24.689)
  Signal2 w0.102: v1(33.325,24.689) 33.381,24.689 34.168,23.901 35.096,23.901 36.5,22.497 36.5,21.622 35.382,20.505 35.382,18.6 33.782,17 v1(33.782,15.164)
  Bottom4 w0.102: C11.2 v1(33.782,15.164)
Net1_5: 1.5 R8.1 | length 24.5
  Top1 w0.102: 1.5 31.095,24.582 31.318,24.359 32.436,24.359 33.553,23.241 v1(33.553,22.428)
  Signal2 w0.102: v1(32.893,15.164) 32.436,15.621 31.75,15.621 31.369,15.24 31.369,14.63 30.607,13.868 28.71,13.868 27.813,14.765 27.813,15.486 29.624,17.297 31.191,17.297 33.553,19.66 v1(33.553,22.428)
  Bottom4 w0.102: R8.1 v1@32.893,15.113
Net1_6: 1.6 R7.1 | length 23.4
  Top1 w0.102: 1.6 31.096,23.882 31.267,24.054 32.283,24.054 32.487,23.851 32.487,22.606 v1(32.741,22.352)
  Signal2 w0.102: v1(32.004,15.164) 32.004,14.249 31.42,13.665 28.626,13.665 27.61,14.681 27.61,15.57 29.54,17.501 31.107,17.501 33.325,19.718 33.325,21.768 v1(32.741,22.352)
  Bottom4 w0.102: R7.1 v1(32.004,15.164)
Net1_8: 1.8 C10.2 R6.1 | length 22.8
  Top1 w0.102: 1.8 30.909,22.482 31.648,21.742 33.909,21.742 v1(34.239,22.073)
  Signal2 w0.102: v1(30.226,15.164) 30.226,14.348 29.967,14.089 28.777,14.089 28.016,14.85 28.016,15.402 29.709,17.094 32.655,17.094 34.519,18.957 34.519,21.793 v1(34.239,22.073)
  Bottom4 w0.102: v1(30.226,15.164) C10.2 R6.1
NetC3_2: C3.2 U1.4 | length 1.3
  Bottom4 w0.381: C3.2 38.67,12.7 U1.4
NetC7_1: C7.1 U2.10 | length 1.3
  Bottom4 w0.102: C7.1 24.261,13.339 U2.10
NetC8_2: C8.2 U2.20 | length 1.6
  Bottom4 w0.102: C8.2@22.987,19.101 C8.2 23.761,18.428 U2.20
NetC18_2: C18.2 U4.47 | length 4.8
  Bottom4 w0.102: U4.47 40.54,19.483 40.284,19.228 40.284,18.847 40.64,18.491 41.656,18.491 42.037,18.11 C18.2
NetC19_2: C19.2 U4.31 | length 3.9
  Bottom4 w0.102: U4.31 39.318,29.412 39.649,29.743 40.615,29.743 C19.2
NetD1_2: D1.2 R3.2 | length 5.7
  Bottom4 w0.102: v1(24.105,28.397) 24.536,28.829 R3.2
NetU4_5: U4.5 Y1.1 | length 2.4
  Bottom4 w0.102: Y1.1 28.971,20.386 29.568,20.983 U4.5
NetU4_6: U4.6 Y1.3 | length 2.5
  Bottom4 w0.102: Y1.3 28.768,22.286 29.571,21.483 U4.6
NRST_1: C20.2 J1.2 R13.1 U4.7 | length 40.9
  Top1 w0.102: v1(25.336,19.202) 25.336,18.783 26.391,17.729 31.826,17.729 33.071,18.974 33.071,20.193 ; v1(32.588,20.676) 33.071,20.193 ; v1(45.466,27.287) 44.849,27.287 44.552,27.584 40.386,27.584 39.124,26.322 39.124,25.51 36.246,22.631 36.246,21.641 35.839,21.234 34.874,21.234 33.833,20.193 33.071,20.193
  Bottom4 w0.102: C20.2 v1(25.336,19.202) R13.1 ; U4.7 32.144,21.983 32.588,21.539 v1(32.588,20.676) ; v1(45.466,27.287) 47.338,27.287 47.981,26.645 47.981,22.657 48.616,22.022 J1.2
OLED_SCL_1: 1.10 R5.1 U4.29 | length 27.2
  Top1 w0.102: 1.10 31.166,21.082 31.42,21.336 34.358,21.336 35.204,22.182 v1(35.204,22.581) 35.603,22.581 38.318,25.296 v1(38.318,26.29)
  Signal2 w0.102: v1(28.448,15.164) 28.448,15.519 29.82,16.891 32.74,16.891 34.722,18.873 34.722,22.098 v1(35.204,22.581)
  Bottom4 w0.102: R5.1 v1(28.448,15.164) ; v1(38.318,26.29) U4.29
OLED_SDA_1: 1.11 R4.1 U4.30 | length 27.1
  Top1 w0.102: 1.11 30.821,20.382 31.572,21.133 34.442,21.133 35.331,22.022 v1(35.738,22.022) 35.738,22.428 38.818,25.508 v1(38.818,26.915)
  Signal2 w0.102: v1(29.337,15.164) 29.337,16.104 29.921,16.688 32.824,16.688 34.925,18.789 34.925,21.209 v1(35.738,22.022)
  Bottom4 w0.102: R4.1 v1(29.337,15.164) ; v1(38.818,26.915) U4.30
PA4_1: J1.21 U4.20 | length 32.6
  Signal2 w0.102: v1(33.807,29.718) 34.646,28.88 47.134,28.88 47.676,28.338 47.676,22.674 48.565,21.785 48.565,16.057 47.98,15.472 v1(45.669,15.472)
  Bottom4 w0.102: v1(33.807,29.718) 33.818,29.707 U4.20 ; J1.21 45.667,15.471 v1(45.669,15.472)
PA6_1: J1.23 U4.22 | length 32.5
  Signal2 w0.102: v1(34.807,29.718) 35.442,29.083 47.219,29.083 47.879,28.423 47.879,25.476 47.879,22.758 48.819,21.819 48.819,15.799 47.984,14.964 v1(46.355,14.964)
  Bottom4 w0.102: U4.22 v1@34.818,29.707 ; J1.23 v1@46.349,14.971
PB0_1: J1.19 U4.26 | length 28.9
  Signal2 w0.102: v1(36.818,26.29) 36.818,27.141 38.354,28.677 47.05,28.677 47.473,28.254 47.473,22.165 47.015,21.708 47.015,19.228 47.219,19.025 47.219,16.804 46.379,15.964 v1(46.355,15.964)
  Bottom4 w0.102: v1(36.818,26.29) U4.26 ; J1.19 v1@46.349,15.971
PB1_1: J1.17 U4.27 | length 26.4
  Signal2 w0.102: v1(37.318,26.915) 37.318,27.353 38.438,28.473 46.966,28.473 47.269,28.17 47.269,22.276 46.812,21.819 46.812,19.144 47.015,18.94 47.015,16.889 46.599,16.472 v1(45.669,16.472)
  Bottom4 w0.102: v1(37.318,26.915) U4.27 ; J1.17 45.667,16.471 v1(45.669,16.472)
PC0_1: J2.4 U4.8 | length 12.8
  Signal2 w0.102: v1(23.458,22.192) 23.749,21.901 23.749,21.692 24.917,20.523 30.683,20.523 31.293,21.133 31.293,21.89 v1(31.886,22.483)
  Bottom4 w0.102: J2.4 23.456,22.193 v1(23.458,22.192) ; U4.8 v1(31.886,22.483)
PC1_1: J2.8 U4.9 | length 16.3
  Signal2 w0.102: v1(23.458,23.192) 24.003,22.647 24.003,21.742 25.019,20.726 30.531,20.726 31.064,21.26 31.064,22.454 31.598,22.987 v1(33.071,22.987)
  Bottom4 w0.102: J2.8 23.456,23.193 v1(23.458,23.192) ; U4.9 33.067,22.983 v1(33.071,22.987)
PC8_1: J1.4 U4.39 | length 9.1
  Bottom4 w0.102: U4.39 43.37,23.483 44.044,22.809 44.044,21.768 44.602,21.209 45.959,21.209 47.197,19.971 J1.4
PC13_1: J2.2 U4.2 | length 13.8
  Signal2 w0.102: v1@21.539,21.695 21.539,21.311 22.936,19.914 30.836,19.914 31.266,19.483 v1(31.886,19.483)
  Bottom4 w0.102: v1(21.551,21.695) 21.553,21.693 J2.2 ; U4.2 v1(31.886,19.483)
PC14_1: J2.6 U4.3 | length 15
  Signal2 w0.102: v1@21.552,22.695 22.809,21.438 23.428,21.438 24.749,20.117 30.937,20.117 31.071,19.983 v1(32.511,19.983)
  Bottom4 w0.102: v1(21.551,22.695) 21.553,22.693 J2.6 ; U4.3 v1(32.511,19.983)
PC15_1: J2.10 U4.4 | length 14.6
  Signal2 w0.102: v1(21.551,23.695) 21.669,23.695 22.123,23.241 22.123,22.454 22.885,21.692 23.462,21.692 24.833,20.32 30.767,20.32 30.93,20.483 v1(31.886,20.483)
  Bottom4 w0.102: v1(21.551,23.695) 21.553,23.693 J2.10 ; U4.4 v1(31.886,20.483)
PWM_A1_1: J1.9 U4.16 | length 24.6
  Signal2 w0.102: v1(31.886,26.483) 32.304,26.483 34.682,24.105 35.18,24.105 37.288,21.996 40.835,21.996 42.088,20.744 42.088,19.38 44.602,16.866 46.609,16.866 46.812,17.069 46.812,18.263 46.602,18.472 v1(45.669,18.472) v1@45.637,18.44
  Bottom4 w0.102: U4.16 v1(31.886,26.483) ; J1.9 45.667,18.471 v1(45.669,18.472)
PWM_A2_1: J1.11 U4.17 | length 25.4
  Signal2 w0.102: v1(31.877,28.194) 31.877,28.22 31.94,28.283 34.9,25.324 37.973,25.324 39.675,27.026 40.64,27.026 41.402,26.264 41.402,22.327 42.723,21.006 42.723,19.625 44.383,17.964 v1(46.355,17.964)
  Bottom4 w0.102: v1(31.877,28.194) 32.229,28.194 U4.17 ; J1.11 v1@46.349,17.971
PWM_B1_1: J1.13 U4.35 | length 13.6
  Signal2 w0.102: v1(40.25,25.483) 40.862,25.483 41.199,25.146 41.199,22.242 42.52,20.922 42.52,19.541 44.588,17.472 v1(45.669,17.472)
  Bottom4 w0.102: v1(40.25,25.483) U4.35 ; J1.13 45.667,17.471 v1(45.669,17.472)
PWM_B2_1: J1.15 U4.36 | length 16.2
  Signal2 w0.102: v1(39.625,24.983) 40.692,24.983 40.97,24.705 40.97,22.149 42.291,20.828 42.291,19.482 44.704,17.069 46.126,17.069 v1(46.355,17.297)
  Bottom4 w0.102: v1(39.625,24.983) U4.36 ; J1.15 46.028,16.971 v1(46.355,17.297)
SPI1_MISO_1: J2.12 U4.56 | length 23.7
  Top1 w0.102: v1(23.458,24.192) 23.379,24.192 22.555,23.368 22.555,20.015 25.883,16.688 33.274,16.688 35.762,19.176 v1(36.318,19.176)
  Bottom4 w0.102: J2.12 23.456,24.193 v1(23.458,24.192) ; U4.56 v1(36.318,19.176)
SPI1_MOSI_1: J2.16 U4.23 | length 16.2
  Top1 w0.102: v1(23.458,25.192) 23.49,25.192 24.486,26.187 24.867,26.187 25.366,26.687 26.103,26.687 26.238,26.822 26.238,27.432 26.873,28.067 31.293,28.067 31.699,27.661 34.572,27.661 v1(35.318,26.915)
  Bottom4 w0.102: J2.16 23.456,25.193 v1(23.458,25.192) ; v1(35.318,26.915) U4.23
SPI1_SCK_1: J2.14 U4.21 | length 17.8
  Top1 w0.102: v1(21.551,24.695) 21.557,24.689 23.724,24.689 24.232,25.197 24.867,25.197 25.349,25.679 25.73,25.679 26.441,26.391 26.441,27.348 26.957,27.864 31.209,27.864 31.615,27.457 34.078,27.457 v1(34.62,26.915)
  Bottom4 w0.102: v1(21.551,24.695) 21.553,24.693 J2.14 ; U4.21 34.318,27.217 v1(34.62,26.915)
SPI3_MISO_1: J2.20 U4.52 | length 32.6
  Top1 w0.102: v1(21.565,17.602) 22.885,16.281 33.444,16.281 35.12,17.958 37.937,17.958 38.318,18.339 v1(38.318,19.176)
  Bottom4 w0.102: v1(21.565,17.602) 21.565,17.932 22.377,18.745 22.377,19.634 22.631,19.888 23.589,19.888 24.054,20.353 24.054,25.984 23.851,26.187 22.51,26.187 J2.20 ; U4.52 v1(38.318,19.176)
SPI3_MOSI_1: J2.18 U4.57 | length 28
  Top1 w0.102: v1(21.565,20.094) 21.565,18.313 23.393,16.485 33.36,16.485 35.426,18.551 v1(35.818,18.551)
  Bottom4 w0.102: v1(21.565,20.094) 21.567,20.091 23.504,20.091 23.851,20.438 23.851,25.552 23.724,25.679 22.518,25.679 J2.18 ; U4.57 v1(35.818,18.551)
SPI3_SCK_1: J2.22 U4.51 | length 33
  Top1 w0.102: v1(21.565,16.866) 22.352,16.078 33.528,16.078 35.204,17.755 38.021,17.755 v1(38.818,18.551)
  Bottom4 w0.102: v1(21.565,16.866) 21.565,16.993 22.047,17.475 22.047,18.11 22.581,18.644 22.581,19.55 22.716,19.685 23.673,19.685 24.257,20.269 24.257,26.372 23.959,26.67 22.528,26.67 J2.22 ; U4.51 v1(38.818,18.551)
SWCLK_1: J1.7 U4.49 | length 14.5
  Top1 w0.102: v1(39.818,18.551) 39.818,17.307 41.783,15.342 44.255,15.342 44.856,15.943 44.856,18.39 45.431,18.964 v1(46.355,18.964)
  Bottom4 w0.102: U4.49 v1(39.818,18.551) ; J1.7 v1@46.349,18.971
SWDIO_1: J1.5 U4.46 | length 14.5
  Top1 w0.102: v1(40.157,19.761) 40.157,18.751 40.199,18.709 40.199,18.393 40.157,18.352 40.157,17.255 41.867,15.545 44.171,15.545 44.628,16.002 44.628,18.771 45.33,19.472 v1(45.669,19.472)
  Bottom4 w0.102: v1(40.157,19.761) 40.379,19.983 U4.46 ; J1.5 45.667,19.471 v1(45.669,19.472)
UART1_Rx_1: J2.15 U4.43 | length 27
  Top1 w0.102: v1(25.451,25.195) 25.5,25.146 26.162,24.484 26.162,21.963 24.917,20.718 24.917,18.845 26.237,17.526 32.963,17.526 36.011,20.574 38.692,20.574 39.601,21.483 v1(40.25,21.483)
  Bottom4 w0.102: v1(25.451,25.195) 25.453,25.193 J2.15 ; v1(40.25,21.483) U4.43
UART1_Tx_1: J2.13 U4.42 | length 29
  Top1 w0.102: v1(24.765,24.687) 25.671,24.687 25.959,24.4 25.959,22.047 24.714,20.803 24.714,18.761 26.153,17.323 33.047,17.323 36.095,20.371 39.116,20.371 v1(39.675,20.93)
  Bottom4 w0.102: v1@24.771,24.693 J2.13 ; v1(39.675,20.93) 39.675,21.692 39.954,21.971 41.606,21.971 U4.42
UART4_Rx_1: J2.7 U4.15 | length 12.4
  Signal2 w0.102: v1(25.451,23.195) 25.481,23.165 26.34,23.165 29.158,25.983 32.285,25.983 32.664,25.603 32.664,25.425 v1(32.563,25.324)
  Bottom4 w0.102: v1(25.451,23.195) 25.453,23.193 J2.7 ; U4.15 32.259,25.983 32.563,25.679 v1(32.563,25.324)
UART4_Tx_1: J2.5 U4.14 | length 11.9
  Signal2 w0.102: v1(24.765,22.687) 24.795,22.657 30.048,22.657 31.886,24.495 v1(31.886,25.483)
  Bottom4 w0.102: v1@24.771,22.693 J2.5 ; U4.14 v1(31.886,25.483)
UART5_Rx_1: J2.11 U4.54 | length 25.1
  Top1 w0.102: v1(25.451,24.195) 25.44,24.206 24.486,24.206 24.079,23.8 24.079,21.158 24.308,20.93 24.308,18.593 26.01,16.891 33.19,16.891 36.035,19.736 37.109,19.736 37.318,19.527 v1(37.318,19.176)
  Bottom4 w0.102: v1(25.451,24.195) v1(25.451,24.195) J2.11 ; U4.54 v1(37.318,19.176)
UART5_Tx_1: J2.9 U4.53 | length 24.7
  Top1 w0.102: v1(24.765,23.687) 24.765,23.647 24.282,23.165 24.282,21.242 24.511,21.014 24.511,18.677 26.094,17.094 33.106,17.094 35.976,19.964 37.496,19.964 37.818,19.642 v1(37.818,18.551)
  Bottom4 w0.102: v1@24.771,23.693 J2.9 ; U4.53 v1(37.818,18.551)
USB_DM_1: J1.1 R12.1 | length 4.8
  Signal2 w0.152: v1(43.307,22.2) 43.307,20.955 43.79,20.472 v1(45.669,20.472)
  Bottom4 w0.102: J1.1 45.667,20.471 v1(45.669,20.472)
USB_DM_IN_1: R12.2 U4.44 | length 1.9
  Bottom4 w0.152: U4.44 42.827,20.983 R12.2
USB_DP_1: J1.3 R14.1 | length 4.7
  Signal2 w0.152: v1(43.307,19.837) 44.806,19.837 44.933,19.964 v1(46.355,19.964)
  Bottom4 w0.102: J1.3 46.349,19.971 v1(46.355,19.964)
USB_DP_IN_1: R14.2 U4.45 | length 1.7
  Bottom4 w0.152: U4.45 43.216,20.483 R14.2
VIN: 1.2 C5.2 C6.2 J1.18 J1.20 J1.22 J1.24 U1.1 U1.3 | length 49.8
  Top1 w0.152: 1.2 31.076,26.682 31.42,27.026 32.255,27.026 34.083,25.197 34.083,23.498 v1(34.265,23.317)
  Signal2 w0.152: v1(34.265,23.317) 35.357,23.317 36.271,22.403 36.271,21.717 35.154,20.599 35.154,18.694 33.35,16.891 33.35,14.3 33.833,13.818 39.548,13.818 v1(41.072,15.342)
  Bottom4 w0.152: v1(41.072,15.342) 41.464,15.342 U1.1
  Bottom4 w0.254: J1.22 49.567,15.471 49.569,15.472 ; 47.576,15.471 47.576,16.258 47.789,16.471 J1.18 49.392,16.471 49.569,16.293 v1(49.569,15.972) ; 47.576,15.471 48.076,15.971 J1.20 49.567,15.971 v1(49.569,15.972) ; 47.576,15.471 48.076,14.971 J1.24 49.567,14.971 v1(49.569,14.972) 49.569,15.472 ; 49.569,15.472 v1(49.569,15.972)
  Bottom4 w0.381: U1.3 42.255,13.02 42.824,13.589 C6.2 ; U1.1 42.306,14.92 42.875,14.351 C5.2 C6.2 ; J1.22 47.576,15.471 47.015,14.91 47.015,13.538 46.584,13.106 43.917,13.106 43.434,13.589 C6.2
pads on no net: 1.1 1.13 J1. J2. U2. U2.2 U2.3 U2.4 U2.5 U2.6 U2.7 U2.12 U2.14 U2.15 U2.16 U2.17 U2.19 U2.21 U2.22 U3.5 U3.8

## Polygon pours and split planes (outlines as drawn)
GND on Gnd3 "GND_L03_P000" (solid, remove dead copper, pour order 0): 21.082,30.226 50.038,30.226 50.038,11.938 21.082,11.938
GND on Bottom4 "GND_L04_P001" (solid, remove dead copper, pour order 1): 21.082,30.226 50.038,30.226 50.038,11.938 21.082,11.938
GND on Signal2 "GND_L02_P002" (solid, remove dead copper, pour order 2): 21.082,30.226 50.038,30.226 50.038,11.938 21.082,11.938
GND on Top1 "GND_L01_P003" (solid, remove dead copper, pour order 3): 21.082,30.226 50.038,30.226 50.038,11.938 21.082,11.938

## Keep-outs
Keep-Out Layer:
  the board outline again, w0.254

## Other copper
Top1:
  text "REF" at 23.055,14.199 h2.03

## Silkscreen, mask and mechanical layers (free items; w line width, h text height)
Top Overlay:
  drawing of 2306 lines, arcs and shapes, not listed
  text "GitHub" at 41.096,24.128 h2.29
  text "Repository" at 41.279,22.553 h1.35
  text "OLED 128x80" at 25.146,18.898 h1.52 r90
  text "Dev" at 21.742,16.728 h1.02
  text "Robot  Embedded" at 41.516,15.596 h1.02
  text "Designed by" at 31.111,14.537 h1.02
  text "Ver 1.1" at 27.655,14.478 h1.02
  text "Framework" at 41.567,14.249 h1.27
  text "Pengzhihui" at 27.682,13.013 h1.78
  text "#STM32F4" at 41.554,12.954 h1.4
  text "{" at 37.896,12.456 h5.08
  text "-UNIT-" at 22.139,12.251 h1.78
Bottom Overlay:
  lines w0.178: 43.129,29.667 cw(c43.218,29.324) 43.561,29.413
  text "CAN-EP" at 42.85,29.413 h0.89
  text "IMU" at 30.151,14.994 h1.52
Top Solder:
  rectangle: 22.581,13.767 26.162,15.748
  region: 22.098,29.845 21.463,28.575 22.733,28.575
  lines w2.286: 37.683,13.976 38.725,13.989
Mechanical 1:
  the board outline again, w0.254
Drill Drawing:
  circle w0.254: c23.663,40.255 r0.847
  lines w0.254: 22.817,44.911 24.51,44.911 23.663,43.218 22.817,44.911
  lines w0.381: 21.298,38.265 337.643,38.265 ; 21.298,45.885 337.643,45.885 ; 35.29,34.455 35.29,49.695 ; 50.526,34.455 50.526,49.695 ; 78.458,34.455 78.458,49.695 ; 91.307,34.455 91.307,49.695 ; 109.946,34.455 109.946,49.695 ; 140.163,34.455 140.163,49.695 ; 155.145,34.455 155.145,49.695 ; 174.088,34.455 174.088,49.695 ; 190.594,34.455 190.594,49.695 ; 212.28,34.455 212.28,49.695 ; 246.153,34.455 246.153,49.695 ; 280.027,34.455 280.027,49.695 ; 302.017,34.455 302.017,49.695 ; 21.298,34.455 337.643,34.455 337.643,49.695 21.298,49.695 21.298,34.455
  text "Symbol" at 23.584,47.028 h1.83
  text "Count" at 36.433,47.028 h1.83
  text "Hole Size" at 51.669,47.028 h1.83
  text "Plated" at 79.601,47.028 h1.83
  text "Hole Type" at 92.45,47.028 h1.83
  text "Drill Layer Pair" at 111.089,47.028 h1.83
  text "Via/Pad" at 141.306,47.028 h1.83
  text "Pad Shape" at 156.288,47.028 h1.83
  text "Template" at 175.231,47.028 h1.83
  text "Description" at 191.737,47.028 h1.83
  text "Hole Tolerance (+)" at 213.423,47.028 h1.83
  text "Hole Tolerance (-)" at 247.296,47.028 h1.83
  text "Hole Length" at 281.17,47.028 h1.83
  text "Routed Path Length" at 303.16,47.028 h1.83
  text "4" at 36.433,43.218 h1.52
  text "23.62mil (0.600mm)" at 51.669,43.218 h1.52
  text "NPTH" at 79.601,43.218 h1.52
  text "Round" at 92.45,43.218 h1.52
  text "Top1 - Bottom4" at 111.089,43.218 h1.52
  text "Pad" at 141.306,43.218 h1.52
  text "Rounded" at 156.288,43.218 h1.52
  text "c60hn60" at 175.231,43.218 h1.52
  text "-" at 281.17,43.218 h1.52
  text "-" at 303.16,43.218 h1.52
  text "219" at 36.433,39.408 h1.52
  text "10.00mil (0.254mm)" at 51.669,39.408 h1.52
  text "PTH" at 79.601,39.408 h1.52
  text "Round" at 92.45,39.408 h1.52
  text "Top1 - Bottom4" at 111.089,39.408 h1.52
  text "Via" at 141.306,39.408 h1.52
  text "Rounded" at 156.288,39.408 h1.52
  text "(Mixed)" at 175.231,39.408 h1.52
  text "-" at 281.17,39.408 h1.52
  text "-" at 303.16,39.408 h1.52
  text "223 Total" at 36.433,35.598 h1.52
